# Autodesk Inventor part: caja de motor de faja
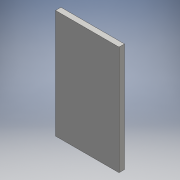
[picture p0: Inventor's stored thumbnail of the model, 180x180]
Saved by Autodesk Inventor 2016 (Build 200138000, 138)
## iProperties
Created: 2016-06
Part Number: caja de motor de faja
Material: Genérico
Document SubType Name: Modeling
Designer: adm
Density: 1 g/cm^3
Appearance: Valor por defecto
Author: adm
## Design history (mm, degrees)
sketch "Boceto1"
  geometry: L1 (-17.5, -1.5)-(17.5, -1.5); L2 (17.5, -1.5)-(17.5, 1.5); L3 (17.5, 1.5)-(-17.5, 1.5); L4 (-17.5, 1.5)-(-17.5, -1.5); L5 (-17.5, -1.5)-(17.5, 1.5); L6 (17.5, -1.5)-(-17.5, 1.5); 1 further point
  constraints: 12 end point, 2 midpoint, 2 parallel, 1 horizontal, 1 perpendicular
  dimensions: "d0" = 35 distance of L3.end L2.end; "d1" = 3 distance of L2.end L1.end
extrude "Extrusión1" new body sketch "Boceto1" distance "d2" = 60; taper "d3" = 0 deg
sketch "Boceto2"
  geometry: 1 further point
node "Sólido1"
